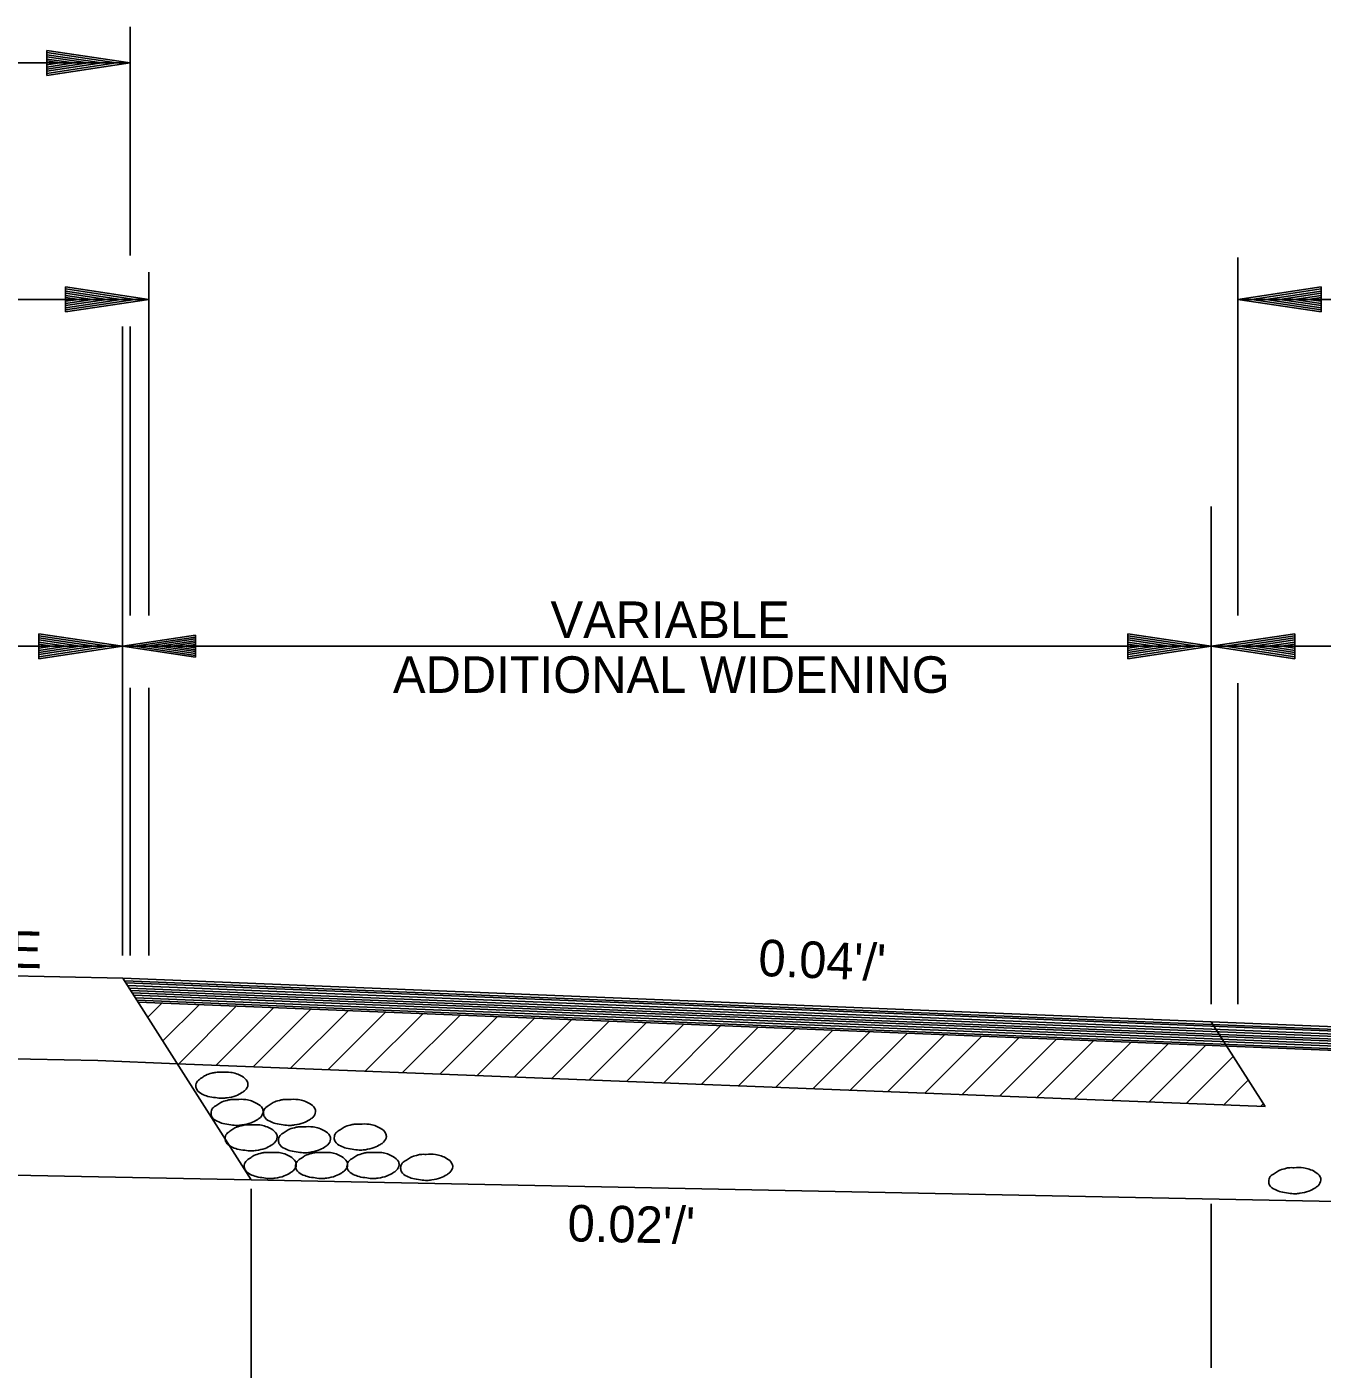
# Model space of a CAD drawing. Extents: x 836 to 5683, y -463 to 1545.
# Drawn here: x 4434.7 to 4647.3, y -331.6 to -111.3 of the extents above; entities that cross this region are included whole.
import ezdxf

# ---------------------------------------------------------------- set-up
doc = ezdxf.new("R2010")
doc.units = 0
doc.layers.add('Default', color=7, linetype='Continuous')

msp = doc.modelspace()

# ---------------------------------------------------------------- linework, layer by layer
at = {"layer": 'Default'}
for p, q in [((4451.68, -111.26), (4451.68, -128.51)), ((4438, -115.15), (4451.68, -117.19)), ((4438, -119.25), (4438, -115.15)), ((4438, -115.48), (4449.41, -117.19)), ((4438, -115.83), (4447.05, -117.19)), ((4438, -116.16), (4444.76, -117.19)), ((4438, -116.55), (4442.44, -117.19)), ((4451.68, -117.19), (4421.83, -117.19)), ((4438, -116.86), (4440.17, -117.19)), ((4438, -119.25), (4451.68, -117.19)), ((4438, -117.87), (4442.44, -117.19)), ((4438, -118.56), (4447.05, -117.19)), ((4438, -118.9), (4449.41, -117.19)), ((4438, -118.2), (4444.76, -117.19)), ((4438, -117.52), (4440.17, -117.19)), ((4451.68, -128.51), (4451.68, -148.78)), ((4633.46, -149.11), (4633.46, -207.86)), ((4454.75, -151.55), (4454.75, -160.46)), ((4441.07, -153.95), (4454.75, -155.99)), ((4441.07, -158.05), (4441.07, -153.95)), ((4647.16, -153.95), (4633.46, -155.99)), ((4647.16, -153.95), (4647.16, -158.05)), ((4454.75, -155.99), (4421.83, -155.99)), ((4441.07, -154.28), (4452.49, -155.99)), ((4441.07, -154.64), (4450.14, -155.99)), ((4441.07, -154.96), (4447.87, -155.99)), ((4441.07, -155.34), (4445.54, -155.99)), ((4441.07, -155.67), (4443.25, -155.99)), ((4441.07, -158.05), (4454.75, -155.99)), ((4441.07, -156.68), (4445.54, -155.99)), ((4441.07, -157.36), (4450.14, -155.99)), ((4441.07, -157.71), (4452.49, -155.99)), ((4441.07, -157.02), (4447.87, -155.99)), ((4441.07, -156.3), (4443.25, -155.99)), ((4647.16, -158.05), (4633.46, -155.99)), ((4954.76, -155.99), (4633.46, -155.99)), ((4647.16, -154.28), (4635.77, -155.99)), ((4647.16, -157.71), (4635.77, -155.99)), ((4647.16, -154.64), (4638.1, -155.99)), ((4647.16, -157.36), (4638.1, -155.99)), ((4647.16, -154.96), (4640.38, -155.99)), ((4647.16, -157.02), (4640.38, -155.99)), ((4647.16, -155.34), (4642.7, -155.99)), ((4647.16, -156.68), (4642.7, -155.99)), ((4647.16, -155.67), (4644.99, -155.99)), ((4647.16, -156.3), (4644.99, -155.99)), ((4450.42, -160.46), (4450.42, -263.71)), ((4451.68, -160.46), (4451.68, -207.86)), ((4454.75, -160.46), (4454.75, -207.86)), ((4629.11, -189.97), (4629.11, -226.62)), ((4436.72, -210.88), (4450.42, -212.92)), ((4436.72, -214.98), (4436.72, -210.88)), ((4436.72, -211.21), (4448.15, -212.92)), ((4462.42, -211.12), (4450.42, -212.92)), ((4462.42, -211.42), (4452.42, -212.92)), ((4462.42, -214.72), (4462.42, -211.12)), ((4615.43, -210.88), (4629.11, -212.92)), ((4615.43, -210.88), (4615.43, -214.98)), ((4615.43, -211.21), (4626.82, -212.92)), ((4642.81, -210.88), (4629.11, -212.92)), ((4642.81, -211.21), (4631.39, -212.92)), ((4642.81, -214.98), (4642.81, -210.88)), ((4450.42, -212.92), (4171.77, -212.92)), ((4436.72, -211.57), (4445.78, -212.92)), ((4436.72, -211.9), (4443.49, -212.92)), ((4436.72, -212.27), (4441.18, -212.92)), ((4436.72, -212.6), (4438.9, -212.92)), ((4436.72, -214.98), (4450.42, -212.92)), ((4436.72, -213.61), (4441.18, -212.92)), ((4436.72, -214.3), (4445.78, -212.92)), ((4436.72, -214.64), (4448.15, -212.92)), ((4436.72, -213.94), (4443.49, -212.92)), ((4436.72, -213.25), (4438.9, -212.92)), ((4450.42, -212.92), (4629.11, -212.92)), ((4462.42, -214.72), (4450.42, -212.92)), ((4462.42, -214.42), (4452.42, -212.92)), ((4462.42, -211.73), (4454.49, -212.92)), ((4462.42, -214.11), (4454.49, -212.92)), ((4462.42, -212.03), (4456.49, -212.92)), ((4462.42, -213.81), (4456.49, -212.92)), ((4462.42, -212.33), (4458.52, -212.92)), ((4462.42, -213.5), (4458.52, -212.92)), ((4462.42, -212.64), (4460.52, -212.92)), ((4462.42, -213.2), (4460.52, -212.92)), ((4615.43, -211.57), (4624.48, -212.92)), ((4615.43, -211.9), (4622.21, -212.92)), ((4615.43, -212.27), (4619.85, -212.92)), ((4615.43, -212.6), (4617.58, -212.92)), ((4615.43, -214.98), (4629.11, -212.92)), ((4615.43, -213.61), (4619.85, -212.92)), ((4615.43, -214.3), (4624.48, -212.92)), ((4615.43, -214.64), (4626.82, -212.92)), ((4615.43, -213.94), (4622.21, -212.92)), ((4615.43, -213.25), (4617.58, -212.92)), ((4629.11, -212.92), (4718.46, -212.92)), ((4642.81, -214.98), (4629.11, -212.92)), ((4642.81, -214.64), (4631.39, -212.92)), ((4642.81, -211.57), (4633.74, -212.92)), ((4642.81, -214.3), (4633.74, -212.92)), ((4642.81, -211.9), (4636.03, -212.92)), ((4642.81, -213.94), (4636.03, -212.92)), ((4642.81, -212.27), (4638.34, -212.92)), ((4642.81, -213.61), (4638.34, -212.92)), ((4642.81, -212.6), (4640.61, -212.92)), ((4642.81, -213.25), (4640.61, -212.92)), ((4451.68, -219.76), (4451.68, -263.71)), ((4454.75, -219.76), (4454.75, -263.71)), ((4629.11, -219.76), (4629.11, -271.69)), ((4633.46, -219), (4633.46, -271.69)), ((4341.89, -265.16), (4450.51, -267.4)), ((4450.51, -267.4), (4471.56, -300.52)), ((4450.52, -267.41), (4718.46, -278.19)), ((4450.81, -267.86), (4718.74, -278.64)), ((4451.02, -268.2), (4718.91, -278.91)), ((4451.3, -268.63), (4719.21, -279.38)), ((4451.57, -269.06), (4719.46, -279.77)), ((4451.81, -269.43), (4719.76, -280.24)), ((4452.05, -269.82), (4719.96, -280.56)), ((4452.3, -270.21), (4720.25, -281.02)), ((4452.57, -270.64), (4720.5, -281.4)), ((4452.82, -271.03), (4720.79, -281.87)), ((4453.03, -271.36), (4720.95, -282.13)), ((4454.59, -273.81), (4456.88, -271.52)), ((4457.06, -277.7), (4463, -271.76)), ((4459.67, -281.46), (4469.12, -272.01)), ((4465.79, -281.7), (4475.23, -272.26)), ((4471.91, -281.94), (4481.35, -272.5)), ((4478.03, -282.18), (4487.47, -272.75)), ((4484.16, -282.43), (4493.59, -272.99)), ((4490.28, -282.67), (4499.71, -273.24)), ((4496.4, -282.91), (4505.83, -273.48)), ((4502.52, -283.15), (4511.94, -273.73)), ((4508.65, -283.39), (4518.06, -273.98)), ((4514.77, -283.63), (4524.18, -274.22)), ((4520.89, -283.88), (4530.3, -274.47)), ((4527.01, -284.12), (4536.42, -274.71)), ((4533.13, -284.36), (4542.53, -274.96)), ((4539.26, -284.6), (4548.65, -275.2)), ((4629.11, -274.6), (4637.93, -288.5)), ((4545.38, -284.84), (4554.77, -275.45)), ((4551.5, -285.08), (4560.89, -275.7)), ((4557.62, -285.33), (4567.01, -275.94)), ((4563.75, -285.57), (4573.13, -276.19)), ((4569.87, -285.81), (4579.24, -276.43)), ((4575.99, -286.05), (4585.36, -276.68)), ((4582.11, -286.29), (4591.48, -276.92)), ((4588.23, -286.53), (4597.6, -277.17)), ((4594.36, -286.78), (4603.72, -277.42)), ((4341.43, -278.87), (4446.4, -280.94)), ((4600.48, -287.02), (4609.83, -277.66)), ((4606.6, -287.26), (4615.95, -277.91)), ((4612.72, -287.5), (4622.07, -278.15)), ((4618.85, -287.74), (4628.19, -278.4)), ((4446.4, -280.94), (4459.44, -281.45)), ((4459.45, -281.45), (4637.93, -288.5)), ((4624.97, -287.98), (4632.7, -280.25)), ((4631.09, -288.23), (4635.17, -284.14)), ((4637.21, -288.47), (4637.64, -288.04)), ((4342, -297.94), (4471.57, -300.53)), ((4471.56, -300.53), (4805.51, -307.21)), ((4471.56, -301.99), (4471.56, -374.56)), ((4629.11, -304.46), (4629.11, -331.37))]:
    msp.add_line(p, q, dxfattribs=at)
for points in [[(4466.67, -282.86), (4468.2, -282.87), (4470.02, -283.51), (4470.91, -284.34), (4471.03, -284.88), (4470.57, -285.8), (4470.05, -286.19), (4469.05, -286.71), (4467.59, -287.05), (4466.83, -287.13), (4465.72, -287.02), (4464.46, -286.81), (4463.51, -286.44), (4462.63, -285.71), (4462.48, -285.13), (4462.74, -284.31), (4463.44, -283.78), (4464.08, -283.36), (4465.1, -283.01), (4465.73, -282.87), (4466.67, -282.86)], [(4469.16, -287.32), (4470.69, -287.33), (4472.51, -287.97), (4473.4, -288.8), (4473.52, -289.34), (4473.06, -290.26), (4472.54, -290.65), (4471.54, -291.17), (4470.08, -291.51), (4469.32, -291.59), (4468.21, -291.48), (4466.95, -291.27), (4466, -290.9), (4465.12, -290.17), (4464.97, -289.59), (4465.23, -288.77), (4465.93, -288.24), (4466.57, -287.82), (4467.59, -287.47), (4468.22, -287.33), (4469.16, -287.32)], [(4477.76, -287.32), (4479.29, -287.33), (4481.11, -287.97), (4482, -288.8), (4482.12, -289.34), (4481.66, -290.26), (4481.14, -290.65), (4480.14, -291.17), (4478.68, -291.51), (4477.92, -291.59), (4476.81, -291.48), (4475.55, -291.27), (4474.6, -290.9), (4473.72, -290.17), (4473.57, -289.59), (4473.83, -288.77), (4474.53, -288.24), (4475.17, -287.82), (4476.19, -287.47), (4476.82, -287.33), (4477.76, -287.32)], [(4471.47, -291.5), (4473, -291.51), (4474.82, -292.15), (4475.71, -292.98), (4475.83, -293.52), (4475.37, -294.44), (4474.85, -294.83), (4473.85, -295.35), (4472.39, -295.69), (4471.63, -295.77), (4470.52, -295.66), (4469.26, -295.45), (4468.31, -295.08), (4467.43, -294.35), (4467.28, -293.77), (4467.54, -292.95), (4468.24, -292.42), (4468.88, -292), (4469.9, -291.65), (4470.53, -291.51), (4471.47, -291.5)], [(4480.22, -291.81), (4481.75, -291.82), (4483.57, -292.46), (4484.46, -293.29), (4484.58, -293.83), (4484.12, -294.75), (4483.6, -295.14), (4482.6, -295.66), (4481.14, -296), (4480.38, -296.08), (4479.27, -295.97), (4478.01, -295.76), (4477.06, -295.39), (4476.18, -294.66), (4476.03, -294.08), (4476.29, -293.26), (4476.99, -292.73), (4477.63, -292.31), (4478.65, -291.96), (4479.28, -291.82), (4480.22, -291.81)], [(4489.38, -291.37), (4490.91, -291.38), (4492.73, -292.02), (4493.62, -292.85), (4493.74, -293.39), (4493.28, -294.31), (4492.76, -294.7), (4491.76, -295.22), (4490.3, -295.56), (4489.54, -295.64), (4488.43, -295.53), (4487.17, -295.32), (4486.22, -294.95), (4485.34, -294.22), (4485.19, -293.64), (4485.45, -292.82), (4486.15, -292.29), (4486.79, -291.87), (4487.81, -291.52), (4488.44, -291.38), (4489.38, -291.37)], [(4474.6, -296.03), (4476.13, -296.04), (4477.95, -296.68), (4478.84, -297.51), (4478.96, -298.05), (4478.5, -298.97), (4477.98, -299.36), (4476.98, -299.88), (4475.52, -300.22), (4474.76, -300.3), (4473.65, -300.19), (4472.39, -299.98), (4471.44, -299.61), (4470.56, -298.88), (4470.41, -298.3), (4470.67, -297.48), (4471.37, -296.95), (4472.01, -296.53), (4473.03, -296.18), (4473.66, -296.04), (4474.6, -296.03)], [(4483.03, -296.03), (4484.56, -296.04), (4486.38, -296.68), (4487.27, -297.51), (4487.39, -298.05), (4486.93, -298.97), (4486.41, -299.36), (4485.41, -299.88), (4483.95, -300.22), (4483.19, -300.3), (4482.08, -300.19), (4480.82, -299.98), (4479.87, -299.61), (4478.99, -298.88), (4478.84, -298.3), (4479.1, -297.48), (4479.8, -296.95), (4480.44, -296.53), (4481.46, -296.18), (4482.09, -296.04), (4483.03, -296.03)], [(4491.47, -296.03), (4493, -296.04), (4494.82, -296.68), (4495.71, -297.51), (4495.83, -298.05), (4495.37, -298.97), (4494.85, -299.36), (4493.85, -299.88), (4492.39, -300.22), (4491.63, -300.3), (4490.52, -300.19), (4489.26, -299.98), (4488.31, -299.61), (4487.43, -298.88), (4487.28, -298.3), (4487.54, -297.48), (4488.24, -296.95), (4488.88, -296.53), (4489.9, -296.18), (4490.53, -296.04), (4491.47, -296.03)], [(4500.27, -296.34), (4501.8, -296.35), (4503.62, -296.99), (4504.51, -297.82), (4504.63, -298.36), (4504.17, -299.28), (4503.65, -299.67), (4502.65, -300.19), (4501.19, -300.53), (4500.43, -300.61), (4499.32, -300.5), (4498.06, -300.29), (4497.11, -299.92), (4496.23, -299.19), (4496.08, -298.61), (4496.34, -297.79), (4497.04, -297.26), (4497.68, -296.84), (4498.7, -296.49), (4499.33, -296.35), (4500.27, -296.34)], [(4642.73, -298.53), (4644.26, -298.54), (4646.08, -299.18), (4646.97, -300.01), (4647.09, -300.55), (4646.63, -301.47), (4646.11, -301.86), (4645.11, -302.38), (4643.65, -302.72), (4642.89, -302.8), (4641.78, -302.69), (4640.52, -302.48), (4639.57, -302.11), (4638.69, -301.38), (4638.54, -300.8), (4638.8, -299.98), (4639.5, -299.45), (4640.14, -299.03), (4641.16, -298.68), (4641.79, -298.54), (4642.73, -298.53)]]:
    msp.add_spline(points, degree=3, dxfattribs=at)

# ---------------------------------------------------------------- texts
for s, p in [('VARIABLE', (4520.68, -211.58)), ('ADDITIONAL WIDENING', (4494.82, -220.58))]:
    msp.add_text(s, height=6, dxfattribs=at).set_placement(p)
for s, rotation, p in [('PROPOSED TRAVEL LANE', 358.8542, (4335.12, -263.74)), ("0.04'/'", 357.7077, (4554.7, -267.03)), ("0.02'/'", 358.8543, (4523.43, -310.6))]:
    msp.add_text(s, height=6, rotation=rotation, dxfattribs=at).set_placement(p)

doc.saveas('drawing.dxf')
